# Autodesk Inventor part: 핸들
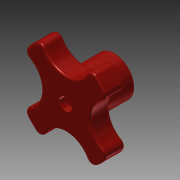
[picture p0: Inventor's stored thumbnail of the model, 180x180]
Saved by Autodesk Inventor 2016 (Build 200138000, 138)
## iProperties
Created: 2018-01
Part Number: 핸들
Material: ABS 플라스틱
Document SubType Name: Modeling
Designer: mduedu
Density: 1 g/cm^3
Appearance: 주황색-빨간색
Author: mduedu
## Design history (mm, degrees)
sketch "스케치1"
  geometry: C1 r 10 at (0, 0); C2 r 25 at (0, 0); 1 further point
  constraints: 2 centre point, 2 coincident
  dimensions: "d0" = 20 diameter of C1; "d1" = 50 diameter of C2
extrude "돌출1" new body sketch "스케치1" distance "d2" = 15; taper "d3" = 0 deg
extrude "돌출2" join sketch "스케치1" distance "d4" = 10; taper "d5" = 0 deg
sketch "스케치2" dims "d8" = 15
  geometry: L1 (-6, -6)-(-4.5, -6); L2 (6, -6)-(6, -4.5); L3 (6, 6)-(4.5, 6); L4 (-6, 6)-(-6, 4.5); L5 (-6, -6)-(6, 6); L6 (6, -6)-(-6, 6); L7 (-4.5, 6)-(-6, 6); L8 (4.5, 6)-(-4.5, 6); L9 (6, 4.5)-(6, 6); L10 (6, -4.5)-(6, 4.5); L11 (4.5, -6)-(6, -6); L12 (-4.5, -6)-(4.5, -6); L13 (-6, -4.5)-(-6, -6); L14 (-6, 4.5)-(-6, -4.5); 2 further points
  constraints: 28 end point, 18 parallel, 9 perpendicular, 3 horizontal, 2 midpoint, 1 coincident, 10 other
  dimensions: "d6" = 12 distance of L4.start L3.start; "d7" = 12 distance of L3.start L2.start
extrude "돌출3" cut sketch "스케치2" distance "d9" = 15; taper "d10" = 0 deg
sketch "스케치3"
  geometry: C1 r 12.5 at (25, 0); 2 further points
  constraints: 2 horizontal alignment, 1 centre point, 1 other
  dimensions: "d14" = 25 diameter of C1
extrude "돌출4" cut sketch "스케치3" stored distance "d15" = 15; taper "d16" = 0 deg
fillet "모깎기1" dims "d20" = 3
fillet "모깎기2" dims "d24" = 1
sketch "스케치4"
  geometry: 2 further points
  constraints: 1 coincident
sketch "스케치5"
  geometry: 2 further points
  constraints: 1 coincident
hole "구멍1" sketch "스케치5" at (0, 0) diameter "d25" = 3.4; stored, may be unused: countersink angle "d29" = 90 deg, drill point angle "d31" = 0 deg; dims "d26" = 6, "d27" = 6.5, "d28" = 3.4, "d30" = 8
node "솔리드1"
pattern_circular "원형 패턴1" dims angle "d18" = 360 deg
pattern_circular "원형 패턴2" dims angle "d22" = 360 deg
node "투영된 루프1"
